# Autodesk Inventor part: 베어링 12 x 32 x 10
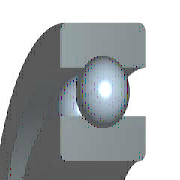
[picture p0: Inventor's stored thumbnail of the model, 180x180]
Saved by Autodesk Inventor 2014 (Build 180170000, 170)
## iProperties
IsCustomPart: 1
Created: 2012-02
Part Number: 베어링 12 x 32 x 10
Material: 강철, 연강
Description: 깊은 그루브 볼 베어링
Document SubType Name: Modeling
Standard: KS B 2023
Designer: test
Standards Organization: KS
Language: ko-KR
Size Designation: 6201 - 12 x 32 x 10
Categories: <MemberInstance><Categories><Category DisplayName="샤프트 부품" InternalName="7f7aeb1f-a693-4053-b835-cee3144e0d98" Mnemonic="SHFT"><Category DisplayName="베어링" Inter
Density: 7.86 g/cm^3
Appearance: 강철
Mass: 32.7519 g
Surface Area: 42.5728 cm^2
Volume: 4.16691 cm^3
Author: test
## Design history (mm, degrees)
sketch "스케치" dims "d0" = 5.2 (= -0.26 x WD + 0.26 x BD)
  geometry: L1 (2.4, 11)-(7.6, 11); L2 (5, 11)-(5, 8.4); L3 (5, 11)-(5, 13.6); L4 (3.068, 9.26)-(0, 9.26); L5 (0, 6)-(10, 6); L6 (3.068, 12.74)-(0, 12.74); L7 (0, 16)-(10, 16); L8 (10, 6)-(10, 9.26); L9 (6.932, 9.26)-(10, 9.26); L10 (6.932, 12.74)-(10, 12.74); L11 (10, 16)-(10, 12.74); L12 (-1.4, 0)-(8.4, 0) reference; L13 (0, -0.3)-(0, 5.3) reference
  constraints: 22 end point, 4 point on line, 2 collinear, 2 perpendicular, 2 symmetric about line, 1 midpoint, 1 parallel, 14 other
  dimensions: "d9" = 12 diameter of L5 L12 (= WD); "d11" = 32 diameter of L7 L12 (= BD); "d12" = 10 distance between parallel lines of L8 L13 (= KB); "d13" = 18.52 diameter of L9 L12 (= 0.326 x BD + 0.674 x WD)
revolve "본체" stored, may be unused: angle "d6" = 90 deg
revolve "볼" stored, may be unused: angle "d7" = 90 deg
pattern_circular "IDS_ARRAYBALL[SIMPL:T]" dims angle "d3" = 360 deg
body "Solid1"
fillet "모깎기1" dims "d1" = 0.6 (= KRS)
other parameters: "WD" = 12 [user parameter; used in 5 equation terms], "BD" = 32 [user parameter; used in 5 equation terms], "KB" = 10 [user parameter; used in 1 equation term], "KRS" = 0.6 [user parameter; used in 1 equation term], "d4" = 0, "d5" = 0, "d8" = 0, "d14" = 0, "d15" = 0, "BBA" = 0 [user parameter], "BC0" = 3100000 [user parameter], "BC" = 6890000 [user parameter], "BR" = 16 (= 0.5 x BD) [user parameter], "WR" = 6 (= 0.5 x WD) [user parameter]
